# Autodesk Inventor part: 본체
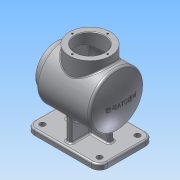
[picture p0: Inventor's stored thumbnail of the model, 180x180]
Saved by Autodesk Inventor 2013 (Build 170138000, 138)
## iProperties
Created: 2016-09
Part Number: 본체
Material: 알루미늄 6061
Document SubType Name: Modeling
Designer: Administrator
Density: 2.71 g/cm^3
Mass: 980.036 g
Surface Area: 1241.54 cm^2
Volume: 361.637 cm^3
Author: Administrator
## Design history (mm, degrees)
sketch "스케치1"
  geometry: L1 (-62, 0)-(-62, 38); L2 (-62, 38)-(-50, 38); L3 (-50, 38)-(-50, 50); L4 (-50, 50)-(48.562, 50); L5 (-87.919, 0)-(60, 0); A1 r 115 centre (-55, 0) between (60, 0) and (48.562, 50); 1 further point
  constraints: 10 end point, 3 perpendicular, 2 point on circle, 2 point on line, 1 centre point, 1 horizontal alignment, 1 parallel, 1 vertical
  dimensions: "d0" = 115 radius of A1; "d2" = 110 distance from line of L3 L5.end; "d5" = 12 distance between parallel lines of L3 L1; "d6" = 100 diameter of L4 L5; "d7" = 76 diameter of L2 L5; "d87" = 50 distance from line of point (0, 0) L3
revolve "회전1" sketch "스케치1" stored, may be unused: angle "d9" = 90 deg
node "작업 평면1"
sketch "스케치2"
  geometry: L1 (-67.5, -50)-(67.5, -50); L2 (67.5, -50)-(67.5, 50); L3 (67.5, 50)-(-67.5, 50); L4 (-67.5, 50)-(-67.5, -50); L5 (-67.5, -50)-(67.5, 50); L6 (67.5, -50)-(-67.5, 50); 1 further point
  constraints: 12 end point, 2 midpoint, 2 parallel, 1 horizontal, 1 perpendicular
  dimensions: "d11" = 135 distance of L2.end L3.end; "d13" = 100 distance of L1.end L2.end
extrude "돌출1" join sketch "스케치2" distance "d14" = 10; taper "d15" = 0 deg
sketch "스케치3"
  geometry: L1 (-5, -40)-(5, -40); L2 (5, -40)-(5, 40); L3 (5, 40)-(-5, 40); L4 (-5, 40)-(-5, -40); L5 (-5, -40)-(5, 40); L6 (5, -40)-(-5, 40); 1 further point
  constraints: 12 end point, 2 midpoint, 2 parallel, 1 horizontal, 1 perpendicular
  dimensions: "d16" = 80 distance of L1.end L2.end; "d18" = 10 distance of L2.end L3.end
extrude "돌출2" join sketch "스케치3" stored distance "d19" = 10; taper "d20" = 0 deg
sketch "스케치4"
  geometry: L1 (-40, -5)-(40, -5); L2 (40, -5)-(40, 5); L3 (40, 5)-(-40, 5); L4 (-40, 5)-(-40, -5); L5 (-40, -5)-(40, 5); L6 (40, -5)-(-40, 5); 1 further point
  constraints: 12 end point, 2 midpoint, 2 parallel, 1 horizontal, 1 perpendicular
  dimensions: "d21" = 80 distance of L2.end L3.end; "d23" = 10 distance of L1.end L2.end
extrude "돌출3" join sketch "스케치4" stored distance "d24" = 10; taper "d25" = 0 deg
feature "면 기울기1" dims angle "d26" = 5 deg
node "작업 평면2"
sketch "스케치5"
  geometry: C1 r 38 at (0, 0); 1 further point
  constraints: 1 centre point, 1 coincident
  dimensions: "d28" = 76 diameter of C1
extrude "돌출4" join sketch "스케치5" stored distance "d30" = 10; taper "d31" = 0 deg
sketch "스케치6"
  geometry: L1 (-62, 27)-(-47, 27); L2 (-47, 27)-(-47, 47); L3 (-47, 47)-(46.661, 47); L4 (-50, 50)-(48.562, 50) reference; L5 (-50, -50)-(-50, 50) reference; L6 (-62, -38)-(-62, 38) reference; L7 (-62, 27)-(-62, 0); L8 (-62, 0)-(57, 0); A1 r 115 centre (-55, 0) between (48.562, -50) and (48.562, 50) reference; A2 r 112 centre (-55, 0) between (57, 0) and (46.661, 47); 1 further point
  constraints: 11 end point, 3 perpendicular, 2 point on circle, 1 centre point, 1 horizontal, 1 midpoint, 1 point on line
  dimensions: "d32" = 3 radial gap between concentric circles of A1 A2; "d33" = 3 distance between parallel lines of L4 L3; "d34" = 3 distance between parallel lines of L2 L5; "d36" = 54 diameter of L1 L8
revolve "회전2" sketch "스케치6" stored, may be unused: angle "d37" = 90 deg
hole "구멍1" diameter "d40" = 54; stored, may be unused: countersink angle "d44" = 90 deg, drill point angle "d46" = 0 deg; dims "d38" = 10, "d39" = 10, "d41" = 6, "d42" = 4, "d43" = 2, "d45" = 40
sketch "스케치7"
  geometry: C1 r 27 at (0, 0) reference; 1 further point
  constraints: 1 vertical alignment
  dimensions: "d47" = 32.5 distance of point (0, 32.5) C1.centre
hole "구멍2" sketch "스케치7" at (0, 32.5) diameter "d48" = 3.242; stored, may be unused: countersink angle "d52" = 90 deg, drill point angle "d54" = 118 deg; dims "d49" = 8, "d50" = 4, "d51" = 2, "d53" = 10
sketch "스케치8"
  geometry: C1 r 27 at (0, 0) reference; 1 further point
  constraints: 1 vertical alignment
  dimensions: "d58" = 32.5 distance of C1.centre point (0, 32.5)
hole "구멍3" sketch "스케치8" at (0, 32.5) diameter "d59" = 3.242; stored, may be unused: countersink angle "d63" = 90 deg, drill point angle "d65" = 118 deg; dims "d60" = 8, "d61" = 4, "d62" = 2, "d64" = 10
fillet "모깎기1" dims "d69" = 5, "d70" = 2, "d71" = 15, "d72" = 3
fillet "모깎기2" dims "d73" = 3
sketch "스케치10"
  geometry: A1 r 12 centre (-52.5, -35) between (-64.5, -35) and (-52.5, -47) reference; A2 r 12 centre (52.5, -35) between (52.5, -47) and (64.5, -35) reference; A3 r 12 centre (52.5, 35) between (64.5, 35) and (52.5, 47) reference; A4 r 12 centre (-52.5, 35) between (-52.5, 47) and (-64.5, 35) reference; 1 further point
hole "구멍4" sketch "스케치10" at (-52.5, 35), (52.5, 35), (52.5, -35), (-52.5, -35) diameter "d74" = 10; stored, may be unused: countersink angle "d78" = 90 deg, drill point angle "d80" = 0 deg; dims "d75" = 8, "d76" = 4, "d77" = 2, "d79" = 20
node "작업 평면3"
sketch "스케치11"
  geometry: 2 further points
  constraints: 1 coincident, 1 other
feature "엠보싱1" sketch "스케치11" dims "d16" = 80, "d18" = 10, "d82" = 0.5, "d83" = 0
chamfer "모따기1" distance "d84" = 1; stored, may be unused: second distance "d85" = 2, angle "d86" = 45 deg
node "솔리드1"
pattern_circular "원형 패턴1" dims angle "d56" = 360 deg
pattern_circular "원형 패턴2" dims angle "d67" = 360 deg
other parameters: "d10" = -82, "d27" = -147
